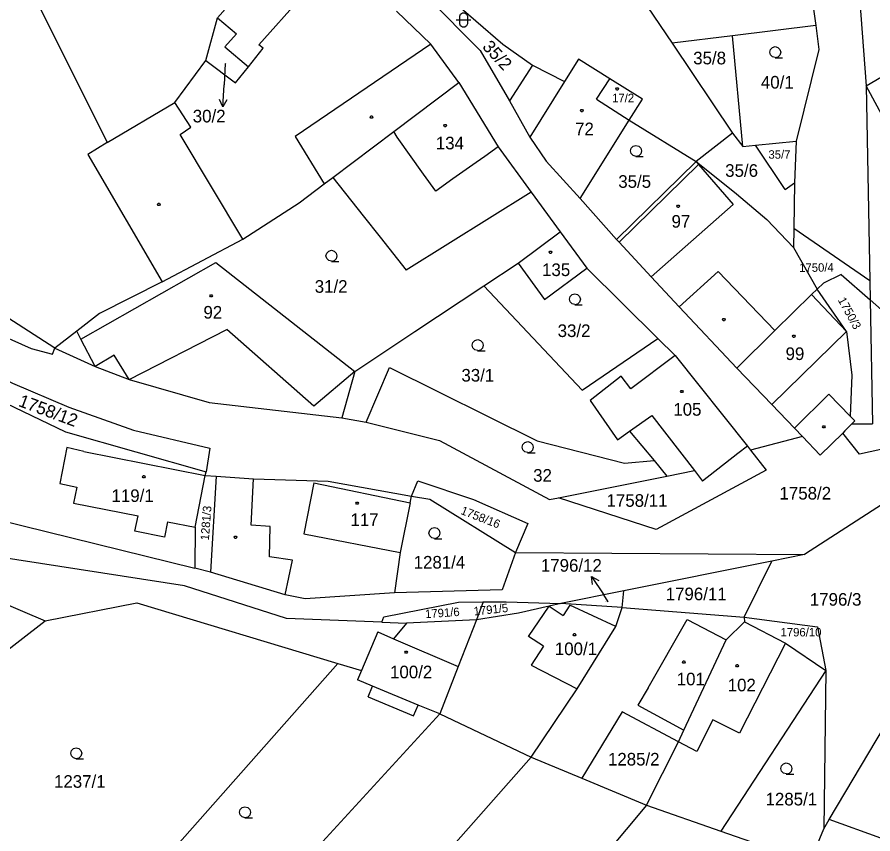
# Model space of a CAD drawing. Extents: x -799786 to -795190, y -1021716 to -1017834.
# Drawn here: x -798163.2 to -798047.9, y -1019191.9 to -1019081.9 of the extents above; entities that cross this region are included whole.
import ezdxf

# ---------------------------------------------------------------- set-up
doc = ezdxf.new("R2010")
doc.units = 0
for name, color, linetype in [('Default', 7, 'Continuous'), ('KN_HRANICE', 7, 'Continuous'), ('KN_KULTURY', 7, 'Continuous'), ('KN_PARCELY', 7, 'Continuous'), ('KN_SLUCKY', 7, 'Continuous')]:
    doc.layers.add(name, color=color, linetype=linetype)

# ---------------------------------------------------------------- blocks, each defined once
blk = doc.blocks.new('304')
at = {"layer": 'Default'}
blk.add_lwpolyline([(0, 0), (-0.38, 0.1), (-0.65, 0.37), (-0.75, 0.74), (-0.65, 1.11), (-0.38, 1.38), (-0.01, 1.48), (0.36, 1.38), (0.63, 1.11), (0.73, 0.73), (0.63, 0.35), (0.36, 0.08), (-0.02, -0.02), (0.98, -0.02)], dxfattribs=at)
blk = doc.blocks.new('316')
at = {"layer": 'Default'}
for points in [[(-0.5, 1.5), (-0.4, 1.79), (-0.15, 1.97), (0.16, 1.97), (0.41, 1.79), (0.51, 1.5), (0.51, 0.5), (0.41, 0.21), (0.16, 0.03), (-0.15, 0.03), (-0.4, 0.21), (-0.5, 0.5), (-0.5, 1.5)], [(-1, 1), (0.27, 1), (1, 1)]]:
    blk.add_lwpolyline(points, dxfattribs=at)
blk = doc.blocks.new('10292')
at = {"layer": 'Default'}
blk.add_line((0, 3), (0, 0), dxfattribs=at)
blk.add_lwpolyline([(-0.5, 2), (0, 3), (0.5, 2)], dxfattribs=at)
blk = doc.blocks.new('402')
at = {"layer": 'Default'}
blk.add_lwpolyline([(0.09, 0.15), (0.18, 0), (0.09, -0.15), (-0.09, -0.15), (-0.18, 0), (-0.09, 0.15), (0.09, 0.15)], dxfattribs=at)

msp = doc.modelspace()

# ---------------------------------------------------------------- linework, layer by layer
at = {"layer": 'KN_HRANICE'}
for p, q in [((-798167.64, -1019065.62), (-798151.06, -1019098.77)), ((-798057.73, -1019066.99), (-798055.57, -1019083.01)), ((-798050.39, -1019069.57), (-798048.79, -1019091.15)), ((-798136.2, -1019081.97), (-798126.47, -1019070.78)), ((-798113.52, -1019073.52), (-798100.81, -1019086.36)), ((-798082.07, -1019074.8), (-798074.93, -1019085.38)), ((-798107.46, -1019077.11), (-798097.74, -1019085.52)), ((-798137.78, -1019087.71), (-798136.2, -1019081.97)), ((-798136.2, -1019081.97), (-798133.66, -1019084.12)), ((-798112.06, -1019081.09), (-798107.47, -1019085.54)), ((-798055.57, -1019083.01), (-798066.78, -1019084.38)), ((-798055.57, -1019083.01), (-798055.14, -1019086.22)), ((-798133.66, -1019084.12), (-798135.24, -1019085.89)), ((-798066.78, -1019084.38), (-798074.93, -1019085.38)), ((-798074.93, -1019085.38), (-798066.81, -1019097.49)), ((-798065.42, -1019099.3), (-798066.78, -1019084.38)), ((-798135.24, -1019085.89), (-798132.04, -1019088.57)), ((-798103.66, -1019090.7), (-798107.47, -1019085.54)), ((-798100.81, -1019086.36), (-798096.85, -1019093.15)), ((-798097.74, -1019085.52), (-798093.76, -1019088.34)), ((-798055.14, -1019086.22), (-798058.23, -1019098.6)), ((-798141.94, -1019093.4), (-798137.78, -1019087.71)), ((-798137.78, -1019087.71), (-798133.76, -1019090.72)), ((-798087.57, -1019087.56), (-798089.44, -1019090.57)), ((-798083.35, -1019090.18), (-798087.57, -1019087.56)), ((-798133.76, -1019090.72), (-798132.04, -1019088.57)), ((-798093.76, -1019088.34), (-798096.85, -1019093.15)), ((-798093.76, -1019088.34), (-798089.44, -1019090.57)), ((-798112.46, -1019097.3), (-798103.66, -1019090.7)), ((-798103.66, -1019090.7), (-798098.38, -1019099.35)), ((-798085.14, -1019092.93), (-798083.35, -1019090.18)), ((-798078.93, -1019092.92), (-798083.35, -1019090.18)), ((-798041.14, -1019105.32), (-798048.79, -1019091.15)), ((-798048.79, -1019091.15), (-798048.29, -1019117.38)), ((-798151.06, -1019098.77), (-798141.94, -1019093.4)), ((-798096.85, -1019093.15), (-798094.09, -1019098.05)), ((-798085.14, -1019092.93), (-798080.71, -1019095.75)), ((-798080.71, -1019095.75), (-798078.93, -1019092.92)), ((-798087.33, -1019106.3), (-798080.71, -1019095.75)), ((-798080.71, -1019095.75), (-798071.7, -1019101.34)), ((-798120.66, -1019103.46), (-798112.46, -1019097.3)), ((-798094.09, -1019098.05), (-798091.9, -1019101.3)), ((-798066.81, -1019097.49), (-798071.7, -1019101.34)), ((-798066.81, -1019097.49), (-798065.42, -1019099.3)), ((-798151.06, -1019098.77), (-798153.69, -1019100.39)), ((-798065.42, -1019099.3), (-798063.71, -1019099.13)), ((-798063.71, -1019099.13), (-798058.23, -1019098.6)), ((-798059.68, -1019105.1), (-798063.71, -1019099.13)), ((-798058.23, -1019098.6), (-798058.44, -1019104.18)), ((-798153.69, -1019100.39), (-798143.65, -1019117.54)), ((-798098.38, -1019099.35), (-798093.91, -1019105.46)), ((-798091.9, -1019101.3), (-798087.33, -1019106.3)), ((-798082.42, -1019111.82), (-798071.7, -1019101.34)), ((-798071.7, -1019101.34), (-798066.26, -1019105.7)), ((-798121.84, -1019104.35), (-798120.66, -1019103.46)), ((-798120.66, -1019103.46), (-798116.57, -1019108.65)), ((-798125.2, -1019106.88), (-798121.84, -1019104.35)), ((-798059.68, -1019105.1), (-798058.44, -1019104.18)), ((-798058.44, -1019104.18), (-798058.54, -1019110.37)), ((-798093.91, -1019105.46), (-798110.8, -1019115.97)), ((-798093.91, -1019105.46), (-798090, -1019110.8)), ((-798066.26, -1019105.7), (-798062.17, -1019109.13)), ((-798132.79, -1019111.77), (-798125.2, -1019106.88)), ((-798087.33, -1019106.3), (-798082.42, -1019111.82)), ((-798116.57, -1019108.65), (-798114.3, -1019111.53)), ((-798058.58, -1019112.89), (-798062.17, -1019109.13)), ((-798095.69, -1019115.04), (-798090, -1019110.8)), ((-798090, -1019110.8), (-798086.45, -1019115.69)), ((-798058.54, -1019110.37), (-798058.58, -1019112.89)), ((-798048.29, -1019117.38), (-798058.54, -1019110.37)), ((-798143.65, -1019117.54), (-798132.79, -1019111.77)), ((-798114.3, -1019111.53), (-798110.8, -1019115.97)), ((-798082.42, -1019111.82), (-798082.09, -1019112.19)), ((-798082.09, -1019112.19), (-798077.74, -1019116.86)), ((-798058.58, -1019112.89), (-798055.37, -1019118.54)), ((-798158.15, -1019126.49), (-798177.44, -1019113.97)), ((-798154.61, -1019125.26), (-798136.43, -1019114.91)), ((-798136.43, -1019114.91), (-798117.69, -1019129.62)), ((-798100.31, -1019118.09), (-798095.69, -1019115.04)), ((-798095.69, -1019115.04), (-798092.14, -1019119.93)), ((-798092.14, -1019119.93), (-798086.45, -1019115.69)), ((-798086.45, -1019115.69), (-798076.84, -1019125.18)), ((-798052.14, -1019116.53), (-798054.53, -1019117.72)), ((-798052.14, -1019116.53), (-798048.24, -1019119.97)), ((-798143.65, -1019117.54), (-798152.13, -1019121.78)), ((-798077.74, -1019116.86), (-798073.98, -1019120.9)), ((-798054.53, -1019117.72), (-798055.37, -1019118.54)), ((-798048.29, -1019117.38), (-798048.24, -1019119.97)), ((-798109.6, -1019124.21), (-798100.31, -1019118.09)), ((-798087.05, -1019132.14), (-798100.31, -1019118.09)), ((-798055.37, -1019118.54), (-798056.14, -1019119.22)), ((-798051.43, -1019124.24), (-798055.37, -1019118.54)), ((-798061.09, -1019124.1), (-798056.14, -1019119.22)), ((-798048.24, -1019119.97), (-798042.83, -1019124.75)), ((-798048.24, -1019119.97), (-798047.92, -1019136.67)), ((-798073.98, -1019120.9), (-798066.23, -1019129.18)), ((-798152.13, -1019121.78), (-798155.18, -1019124.17)), ((-798155.18, -1019124.17), (-798158.15, -1019126.49)), ((-798154.61, -1019125.26), (-798155.18, -1019124.17)), ((-798117.69, -1019129.62), (-798109.6, -1019124.21)), ((-798066.23, -1019129.18), (-798061.09, -1019124.1)), ((-798051.43, -1019124.24), (-798050.7, -1019130.11)), ((-798087.05, -1019132.14), (-798076.84, -1019125.18)), ((-798076.84, -1019125.18), (-798074.52, -1019127.48)), ((-798158.15, -1019126.49), (-798152.69, -1019128.93)), ((-798074.52, -1019127.48), (-798080.48, -1019131.95)), ((-798074.52, -1019127.48), (-798064.78, -1019139.67)), ((-798152.69, -1019128.93), (-798148.09, -1019130.7)), ((-798116.19, -1019136.45), (-798113.03, -1019129.07)), ((-798113.03, -1019129.07), (-798093.11, -1019138.95)), ((-798066.23, -1019129.18), (-798061.5, -1019134.08)), ((-798117.69, -1019129.62), (-798119.44, -1019135.87)), ((-798081.8, -1019130.25), (-798086, -1019133.51)), ((-798080.48, -1019131.95), (-798081.8, -1019130.25)), ((-798050.7, -1019130.11), (-798050.92, -1019135.62)), ((-798148.09, -1019130.7), (-798137.33, -1019133.77)), ((-798166.41, -1019133.11), (-798156.68, -1019137.76)), ((-798137.33, -1019133.77), (-798119.44, -1019135.87)), ((-798086, -1019133.51), (-798082.3, -1019138.84)), ((-798058.42, -1019137.25), (-798061.5, -1019134.08)), ((-798119.44, -1019135.87), (-798116.19, -1019136.45)), ((-798050.92, -1019135.62), (-798050.3, -1019136.25)), ((-798116.19, -1019136.45), (-798106.29, -1019138.89)), ((-798057.35, -1019138.35), (-798058.42, -1019137.25)), ((-798050.71, -1019136.66), (-798051.64, -1019137.61)), ((-798050.3, -1019136.25), (-798050.71, -1019136.66)), ((-798050.71, -1019136.66), (-798047.92, -1019136.67)), ((-798156.68, -1019137.76), (-798137.74, -1019143.13)), ((-798082.3, -1019138.84), (-798080.66, -1019137.63)), ((-798080.66, -1019137.63), (-798077.35, -1019141.62)), ((-798057.35, -1019138.35), (-798064.36, -1019140.21)), ((-798054.97, -1019140.87), (-798057.35, -1019138.35)), ((-798051.93, -1019137.9), (-798054.97, -1019140.87)), ((-798051.64, -1019137.61), (-798051.93, -1019137.9)), ((-798049.66, -1019140.75), (-798051.93, -1019137.9)), ((-798106.29, -1019138.89), (-798091.47, -1019146.85)), ((-798093.11, -1019138.95), (-798081.37, -1019141.96)), ((-798064.78, -1019139.67), (-798066.07, -1019140.67)), ((-798064.78, -1019139.67), (-798064.36, -1019140.21)), ((-798066.07, -1019140.67), (-798070.82, -1019144.37)), ((-798046.79, -1019140.13), (-798049.66, -1019140.75)), ((-798081.37, -1019141.96), (-798077.35, -1019141.62)), ((-798077.35, -1019141.62), (-798075.63, -1019143.7)), ((-798037.82, -1019141.78), (-798057.09, -1019154.27)), ((-798137.85, -1019143.62), (-798137.74, -1019143.13)), ((-798075.63, -1019143.7), (-798071.91, -1019142.96)), ((-798071.91, -1019142.96), (-798070.82, -1019144.37)), ((-798139.22, -1019150.58), (-798137.85, -1019143.62)), ((-798137.85, -1019143.62), (-798136.37, -1019143.7)), ((-798136.37, -1019143.7), (-798137.17, -1019156.65)), ((-798136.37, -1019143.7), (-798131.36, -1019144.06)), ((-798131.36, -1019144.06), (-798121.3, -1019144.37)), ((-798090.24, -1019146.61), (-798075.63, -1019143.7)), ((-798121.3, -1019144.37), (-798110.08, -1019146.39)), ((-798182.05, -1019145.56), (-798139.27, -1019156.11)), ((-798110.25, -1019147.31), (-798110.08, -1019146.39)), ((-798110.08, -1019146.39), (-798107.61, -1019146.83)), ((-798110.25, -1019147.31), (-798111.59, -1019153.98)), ((-798107.61, -1019146.83), (-798096.03, -1019153.99)), ((-798091.47, -1019146.85), (-798090.24, -1019146.61)), ((-798139.22, -1019150.58), (-798139.27, -1019156.11)), ((-798140.66, -1019158.48), (-798169.21, -1019154.08)), ((-798111.59, -1019153.98), (-798112.36, -1019159.45)), ((-798096.03, -1019153.99), (-798097.83, -1019159.01)), ((-798096.03, -1019153.99), (-798057.09, -1019154.27)), ((-798057.09, -1019154.27), (-798061.5, -1019155.15)), ((-798061.5, -1019155.15), (-798081.46, -1019159.16)), ((-798065.21, -1019162.72), (-798061.5, -1019155.15)), ((-798137.17, -1019156.65), (-798139.27, -1019156.11)), ((-798127.1, -1019159.69), (-798137.17, -1019156.65)), ((-798174.14, -1019157.02), (-798159.42, -1019163.19)), ((-798126.89, -1019162.88), (-798140.66, -1019158.48)), ((-798097.83, -1019159.01), (-798112.36, -1019159.45)), ((-798081.46, -1019159.16), (-798089.94, -1019160.86)), ((-798081.68, -1019161.39), (-798081.46, -1019159.16)), ((-798124.38, -1019160.26), (-798127.1, -1019159.69)), ((-798112.36, -1019159.45), (-798124.38, -1019160.26)), ((-798159.42, -1019163.19), (-798147.09, -1019160.78)), ((-798147.09, -1019160.78), (-798119.98, -1019168.95)), ((-798100.39, -1019160.66), (-798101.32, -1019163.05)), ((-798091.51, -1019161.22), (-798095.64, -1019162.15)), ((-798089.94, -1019160.86), (-798091.51, -1019161.22)), ((-798081.68, -1019161.39), (-798089.94, -1019160.86)), ((-798082.54, -1019163.96), (-798081.68, -1019161.39)), ((-798081.68, -1019161.39), (-798065.21, -1019162.72)), ((-798095.64, -1019162.15), (-798101.32, -1019163.05)), ((-798065.21, -1019162.72), (-798065.17, -1019163.35)), ((-798065.21, -1019162.72), (-798055.32, -1019164.01)), ((-798183.97, -1019182.09), (-798159.42, -1019163.19)), ((-798114.07, -1019163.4), (-798126.89, -1019162.88)), ((-798114.07, -1019163.4), (-798110.73, -1019163.53)), ((-798110.73, -1019163.53), (-798112.48, -1019165.62)), ((-798101.32, -1019163.05), (-798110.73, -1019163.53)), ((-798101.32, -1019163.05), (-798103.77, -1019169.34)), ((-798067.63, -1019165.76), (-798065.17, -1019163.35)), ((-798065.17, -1019163.35), (-798059.65, -1019166.21)), ((-798114.58, -1019164.7), (-798116.8, -1019169.89)), ((-798114.58, -1019164.7), (-798112.48, -1019165.62)), ((-798087.75, -1019172.37), (-798082.54, -1019163.96)), ((-798055.32, -1019164.01), (-798054.22, -1019169.88)), ((-798073.36, -1019177.94), (-798067.63, -1019165.76)), ((-798059.65, -1019166.21), (-798054.22, -1019169.88)), ((-798053.76, -1019189.97), (-798040.62, -1019167.84)), ((-798119.98, -1019168.95), (-798158.02, -1019211.88)), ((-798119.98, -1019168.95), (-798116.8, -1019169.89)), ((-798103.77, -1019169.34), (-798106.25, -1019175.74)), ((-798116.8, -1019169.89), (-798117.34, -1019171.17)), ((-798054.22, -1019169.88), (-798068.37, -1019191.52)), ((-798054.22, -1019169.88), (-798054.49, -1019191.2)), ((-798115.3, -1019172.01), (-798117.34, -1019171.17)), ((-798115.89, -1019173.44), (-798115.3, -1019172.01)), ((-798093.94, -1019181.55), (-798087.75, -1019172.37)), ((-798115.89, -1019173.44), (-798109.78, -1019176.02)), ((-798109.78, -1019176.02), (-798109.16, -1019174.54)), ((-798106.25, -1019175.74), (-798109.16, -1019174.54)), ((-798106.25, -1019175.74), (-798146.5, -1019219.57)), ((-798106.25, -1019175.74), (-798093.94, -1019181.55)), ((-798081.68, -1019175.47), (-798087.09, -1019184.41)), ((-798074.09, -1019179.49), (-798081.68, -1019175.47)), ((-798074.09, -1019179.49), (-798073.36, -1019177.94)), ((-798078.38, -1019188.04), (-798074.09, -1019179.49)), ((-798093.94, -1019181.55), (-798134.55, -1019227.54)), ((-798093.94, -1019181.55), (-798087.09, -1019184.41)), ((-798087.09, -1019184.41), (-798078.38, -1019188.04)), ((-798078.38, -1019188.04), (-798119.93, -1019237.3)), ((-798078.38, -1019188.04), (-798068.37, -1019191.52)), ((-798054.49, -1019191.2), (-798053.76, -1019189.97)), ((-798046.82, -1019192.47), (-798053.76, -1019189.97)), ((-798068.37, -1019191.52), (-798060.24, -1019194.35)), ((-798056.57, -1019196.32), (-798054.49, -1019191.2))]:
    msp.add_line(p, q, dxfattribs=at)
for points in [[(-798180.57, -1019113.69), (-798175.77, -1019118.66), (-798166.98, -1019124), (-798161.34, -1019126.51), (-798158.43, -1019127.29), (-798158.15, -1019126.49)], [(-798173.18, -1019126.48), (-798169.57, -1019128.51), (-798163.84, -1019131.17), (-798156.24, -1019134.41), (-798147.55, -1019137.5), (-798137.22, -1019139.95), (-798137.74, -1019143.13)], [(-798064.36, -1019140.21), (-798062.26, -1019142.91), (-798077.1, -1019150.9), (-798090.24, -1019146.61)], [(-798110.08, -1019146.39), (-798109.22, -1019144.34), (-798101.71, -1019146.87), (-798094.36, -1019150.08), (-798096.03, -1019153.99)], [(-798114.07, -1019163.4), (-798113.8, -1019162.68), (-798103.71, -1019160.7), (-798100.39, -1019160.66)], [(-798100.39, -1019160.66), (-798097.28, -1019160.62), (-798089.94, -1019160.86)]]:
    msp.add_lwpolyline(points, dxfattribs=at)
at = {"layer": 'KN_PARCELY'}
for p, q in [((-798135.19, -1019088.14), (-798135.33, -1019090.98)), ((-798083.56, -1019160.63), (-798084.15, -1019159.72))]:
    msp.add_line(p, q, dxfattribs=at)
at = {"layer": 'KN_SLUCKY'}
for p, q in [((-798121.12, -1019074.97), (-798130.62, -1019085.59)), ((-798048.79, -1019091.15), (-798038.3, -1019084.86)), ((-798132.04, -1019088.57), (-798130.03, -1019086.08)), ((-798130.03, -1019086.08), (-798130.62, -1019085.59)), ((-798107.47, -1019085.54), (-798125.72, -1019097.97)), ((-798089.44, -1019090.57), (-798094.09, -1019098.05)), ((-798139.82, -1019096.7), (-798141.94, -1019093.4)), ((-798141.25, -1019097.7), (-798139.82, -1019096.7)), ((-798132.79, -1019111.77), (-798141.25, -1019097.7)), ((-798125.72, -1019097.97), (-798121.84, -1019104.35)), ((-798111.98, -1019098.06), (-798112.46, -1019097.3)), ((-798108.45, -1019103.03), (-798111.98, -1019098.06)), ((-798098.38, -1019099.35), (-798100.19, -1019100.63)), ((-798101.33, -1019101.44), (-798104.47, -1019103.67)), ((-798100.19, -1019100.63), (-798101.33, -1019101.44)), ((-798071.7, -1019101.34), (-798071.37, -1019101.71)), ((-798082.09, -1019112.19), (-798071.37, -1019101.71)), ((-798071.37, -1019101.71), (-798066.69, -1019107.14)), ((-798106.79, -1019105.33), (-798108.45, -1019103.03)), ((-798104.47, -1019103.67), (-798106.79, -1019105.33)), ((-798077.74, -1019116.86), (-798066.69, -1019107.14)), ((-798073.98, -1019120.9), (-798068.72, -1019116.15)), ((-798068.72, -1019116.15), (-798061.09, -1019124.1)), ((-798056.14, -1019119.22), (-798051.43, -1019124.24)), ((-798148.09, -1019130.7), (-798134.95, -1019123.95)), ((-798123.21, -1019134.28), (-798134.95, -1019123.95)), ((-798061.5, -1019134.08), (-798051.43, -1019124.24)), ((-798152.69, -1019128.93), (-798154.61, -1019125.26)), ((-798150.15, -1019127.4), (-798152.69, -1019128.93)), ((-798148.09, -1019130.7), (-798150.15, -1019127.4)), ((-798117.69, -1019129.62), (-798123.21, -1019134.28)), ((-798058.42, -1019137.25), (-798053.81, -1019132.66)), ((-798053.81, -1019132.66), (-798050.92, -1019135.62)), ((-798080.66, -1019137.63), (-798077.65, -1019135.54)), ((-798077.65, -1019135.54), (-798071.91, -1019142.96)), ((-798154.22, -1019140.4), (-798137.85, -1019143.62)), ((-798131.66, -1019150.32), (-798131.36, -1019144.06)), ((-798155.16, -1019145.21), (-798155.6, -1019147.34)), ((-798123.23, -1019144.63), (-798124.59, -1019151.5)), ((-798123.23, -1019144.63), (-798110.25, -1019147.31)), ((-798155.6, -1019147.34), (-798146.92, -1019149.07)), ((-798147.33, -1019151.13), (-798146.92, -1019149.07)), ((-798142.95, -1019149.85), (-798143.35, -1019151.91)), ((-798142.95, -1019149.85), (-798139.22, -1019150.58)), ((-798143.35, -1019151.91), (-798147.33, -1019151.13)), ((-798129.11, -1019150.51), (-798131.66, -1019150.32)), ((-798129.2, -1019154.56), (-798129.11, -1019150.51)), ((-798124.59, -1019151.5), (-798111.59, -1019153.98)), ((-798126.11, -1019155.03), (-798129.2, -1019154.56)), ((-798127.1, -1019159.69), (-798126.11, -1019155.03)), ((-798091.51, -1019161.22), (-798089.61, -1019162.49)), ((-798088.71, -1019161.09), (-798089.61, -1019162.49)), ((-798082.54, -1019163.96), (-798088.71, -1019161.09)), ((-798078.14, -1019172.21), (-798072.9, -1019163.01)), ((-798072.9, -1019163.01), (-798067.63, -1019165.76)), ((-798112.48, -1019165.62), (-798103.77, -1019169.34)), ((-798059.65, -1019166.21), (-798065.83, -1019178.34)), ((-798092.29, -1019166.63), (-798093.93, -1019169.17)), ((-798093.93, -1019169.17), (-798087.75, -1019172.37)), ((-798109.16, -1019174.54), (-798115.3, -1019172.01)), ((-798078.14, -1019172.21), (-798079.57, -1019174.56)), ((-798079.57, -1019174.56), (-798073.36, -1019177.94)), ((-798069.46, -1019176.52), (-798071.61, -1019180.82)), ((-798065.83, -1019178.34), (-798069.46, -1019176.52)), ((-798071.61, -1019180.82), (-798074.09, -1019179.49))]:
    msp.add_line(p, q, dxfattribs=at)
for points in [[(-798154.22, -1019140.4), (-798156.5, -1019139.86), (-798157.46, -1019144.72), (-798155.16, -1019145.21)], [(-798092.29, -1019166.63), (-798094.29, -1019165.29), (-798091.51, -1019161.22)]]:
    msp.add_lwpolyline(points, dxfattribs=at)

# ---------------------------------------------------------------- block references
at = {"layer": 'KN_KULTURY'}
for name, p in [('316', (-798103.04, -1019083.26)), ('304', (-798061.03, -1019087.33)), ('402', (-798082.33, -1019091.55)), ('402', (-798087.11, -1019094.47)), ('402', (-798115.45, -1019095.34)), ('402', (-798105.51, -1019096.49)), ('304', (-798079.8, -1019100.63)), ('402', (-798144.13, -1019107.11)), ('402', (-798074.11, -1019107.36)), ('304', (-798120.84, -1019114.77)), ('402', (-798091.32, -1019113.56)), ('402', (-798137.06, -1019119.42)), ('304', (-798088.03, -1019120.61)), ('402', (-798067.97, -1019122.63)), ('304', (-798101.13, -1019126.8)), ('402', (-798058.55, -1019124.87)), ('402', (-798073.64, -1019132.31)), ('402', (-798054.49, -1019137.07)), ('304', (-798094.39, -1019140.54)), ('402', (-798146.14, -1019143.79)), ('402', (-798117.4, -1019147.35)), ('304', (-798106.96, -1019152.12)), ('402', (-798133.79, -1019151.94)), ('402', (-798088.07, -1019165.07)), ('402', (-798110.8, -1019167.42)), ('402', (-798073.37, -1019168.76)), ('402', (-798066.18, -1019169.25)), ('304', (-798155.24, -1019181.77)), ('304', (-798059.53, -1019183.83)), ('304', (-798132.49, -1019189.72))]:
    msp.add_blockref(name, p, dxfattribs=at)
at = {"layer": 'KN_PARCELY'}
for p, rotation in [((-798135.33, -1019090.98), 177.15855), ((-798084.15, -1019159.72), 33.116960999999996)]:
    msp.add_blockref('10292', p, dxfattribs=dict(at, rotation=rotation))

# ---------------------------------------------------------------- texts
for s, height, rotation, p in [('35/2', 1.7, 312.606, (-798100.61, -1019085.95)), ('1750/4', 1.14, 0.917, (-798057.8, -1019116.22)), ('1750/3', 1.14, 298.74, (-798052.63, -1019119.98)), ('1758/12', 1.7, 339.592, (-798163.15, -1019134.24)), ('1281/3', 1.14, 85.6, (-798137.37, -1019152.4)), ('1758/16', 1.14, 338.675, (-798103.52, -1019148.78)), ('1791/6', 1.14, 3.839, (-798108.19, -1019162.85)), ('1791/5', 1.14, 6.073, (-798101.62, -1019162.49))]:
    msp.add_text(s, height=height, rotation=rotation, dxfattribs=at).set_placement(p)
for s, height, p in [('35/8', 1.7, (-798072.09, -1019088.24)), ('30/2', 0.1, (-798135.18, -1019088.14)), ('40/1', 1.7, (-798062.97, -1019091.5)), ('17/2', 1.14, (-798083.02, -1019093.34)), ('30/2', 1.7, (-798139.54, -1019096.06)), ('72', 1.7, (-798088.01, -1019097.79)), ('134', 1.7, (-798106.78, -1019099.69)), ('35/7', 1.14, (-798061.95, -1019100.95)), ('35/6', 1.7, (-798067.78, -1019103.39)), ('35/5', 1.7, (-798082.19, -1019104.87)), ('97', 1.7, (-798075.01, -1019110.24)), ('135', 1.7, (-798092.46, -1019116.76)), ('31/2', 1.7, (-798123.1, -1019119.01)), ('92', 1.7, (-798138.1, -1019122.49)), ('33/2', 1.7, (-798090.36, -1019124.97)), ('99', 1.7, (-798059.64, -1019128.07)), ('33/1', 1.7, (-798103.33, -1019130.97)), ('105', 1.7, (-798074.77, -1019135.57)), ('32', 1.7, (-798093.66, -1019144.46)), ('119/1', 1.7, (-798150.49, -1019147.19)), ('1758/2', 1.7, (-798060.46, -1019146.86)), ('1758/11', 1.7, (-798083.77, -1019147.84)), ('117', 1.7, (-798118.28, -1019150.42)), ('1281/4', 1.7, (-798109.77, -1019156.16)), ('1796/12', 1.7, (-798092.62, -1019156.58)), ('1796/11', 1.7, (-798075.8, -1019160.43)), ('1796/3', 1.7, (-798056.37, -1019161.16)), ('1796/12', 0.1, (-798083.91, -1019160.63)), ('1796/10', 1.14, (-798060.32, -1019165.3)), ('100/1', 1.7, (-798090.74, -1019167.82)), ('100/2', 1.7, (-798112.95, -1019170.94)), ('101', 1.7, (-798074.31, -1019171.89)), ('102', 1.7, (-798067.44, -1019172.7)), ('1285/2', 1.7, (-798083.58, -1019182.69)), ('1237/1', 1.7, (-798158.24, -1019185.69)), ('1285/1', 1.7, (-798062.34, -1019188.07))]:
    msp.add_text(s, height=height, dxfattribs=at).set_placement(p)

doc.saveas('drawing.dxf')
